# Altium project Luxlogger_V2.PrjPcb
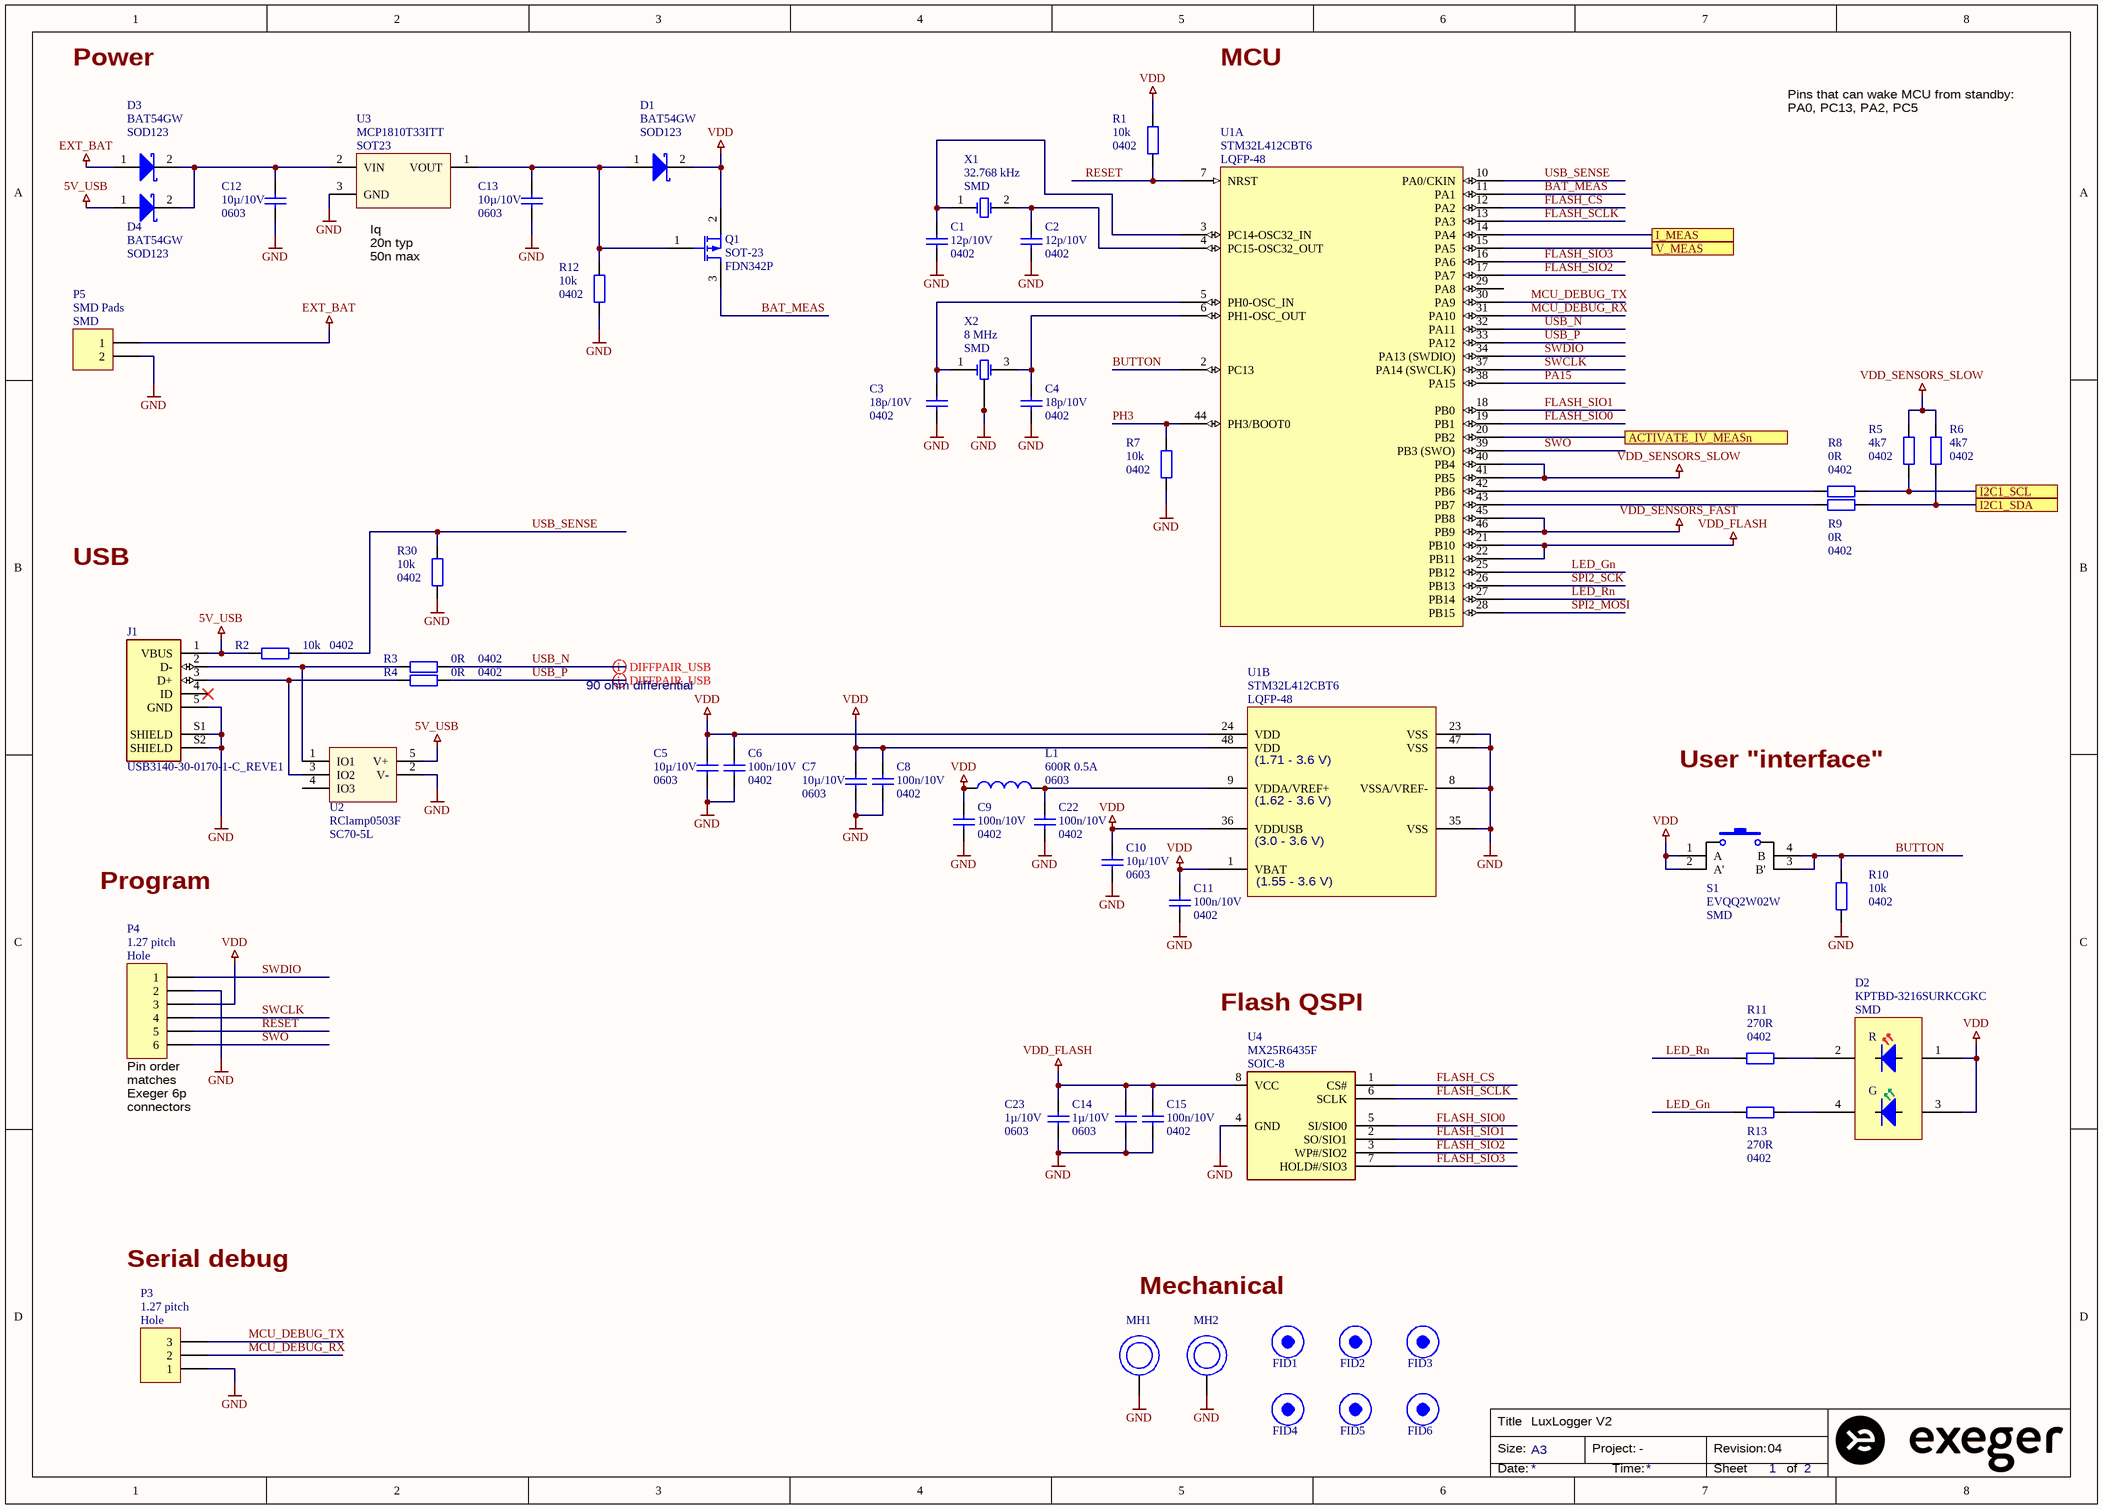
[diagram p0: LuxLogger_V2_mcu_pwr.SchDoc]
CompanyName: Exeger Operations AB; PROJ_Project: -; PROJ_Revision: 04; PROJ_Title: LuxLogger V2; Title: LuxLogger V2
3 sheets, 85 parts. Net scope: flat (ports and power ports of the same name join across sheets).
Board file: LuxLogger_V2_pcb.PcbDoc
Sheets:
  LuxLogger_V2_mcu_pwr.SchDoc
  LuxLogger_V2_sensors.SchDoc
  Sunboost.SchDoc

## Sheet LuxLogger_V2_mcu_pwr.SchDoc: LuxLogger V2
size A3; Engineer: ChEn; SheetNumber: 1; SheetTotal: 2

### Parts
(Parts that share a designator on the sheet are numbered #1, #2 ... from top to bottom, then left to right.)
C1  Specification: 12p/10V  Package: 0402  [CAP0402]
C2  Specification: 12p/10V  Package: 0402  [CAP0402]
C3  Specification: 18p/10V  Package: 0402  [CAP0402]
C4  Specification: 18p/10V  Package: 0402  [CAP0402]
C5  Specification: 10µ/10V  Package: 0603  [CAP0603]
C6  Specification: 100n/10V  Package: 0402  [CAP0402]
C7  Specification: 10µ/10V  Package: 0603  [CAP0603]
C8  Specification: 100n/10V  Package: 0402  [CAP0402]
C9  Specification: 100n/10V  Package: 0402  [CAP0402]
C10  Specification: 10µ/10V  Package: 0603  [CAP0603]
C11  Specification: 100n/10V  Package: 0402  [CAP0402]
C12  Specification: 10µ/10V  Package: 0603  [CAP0603]
C13  Specification: 10µ/10V  Package: 0603  [CAP0603]
C14  Specification: 1µ/10V  Package: 0603  [CAP0603]
C15  Specification: 100n/10V  Package: 0402  [CAP0402]
C22  Specification: 100n/10V  Package: 0402  [CAP0402]
C23  Specification: 1µ/10V  Package: 0603  [CAP0603]
D1  Package: SOD123  Specification: BAT54GW  [SOD123 SODFL360X130-2N]  (hidden comment: Alternative ON BAT54T1GOSCT-ND)
D2  Package: SMD  [KPTBD-3216SURKCGKC]
D3  Package: SOD123  Specification: BAT54GW  [SOD123 SODFL360X130-2N]  (hidden comment: Alternative ON BAT54T1GOSCT-ND)
D4  Package: SOD123  Specification: BAT54GW  [SOD123 SODFL360X130-2N]  (hidden comment: Alternative ON BAT54T1GOSCT-ND)
FID1  Fiducial  [FIDUCIAL_02_small]  (value not drawn)  (no BOM)
FID2  Fiducial  [FIDUCIAL_02_small]  (value not drawn)  (no BOM)
FID3  Fiducial  [FIDUCIAL_02_small]  (value not drawn)  (no BOM)
FID4  Fiducial  [FIDUCIAL_02_small]  (value not drawn)  (no BOM)
FID5  Fiducial  [FIDUCIAL_02_small]  (value not drawn)  (no BOM)
FID6  Fiducial  [FIDUCIAL_02_small]  (value not drawn)  (no BOM)
J1  USB3140-30-0170-1-C_REVE1  [GCT_USB3140-30-0170-1-C_REVE1]
L1  Specification: 600R 0.5A  Package: 0603  [CAP0603]
MH1  Mounting hole  [HOLE_PLATED_2300um]  (value not drawn)  (no BOM)
MH2  Mounting hole  [HOLE_PLATED_2300um]  (value not drawn)  (no BOM)
P3#1  Package: Hole  Specification: 1.27 pitch  [Header 1x3 1.27]  (no BOM)
P4  Package: Hole  Specification: 1.27 pitch  [Header 1x6 1.27]  (no BOM)
P5  Package: SMD  Specification: SMD Pads  [2x1 blank pads_2]  (no BOM)
Q1  Package: SOT-23  Specification: FDN342P  [SOT23-3]
R1  Package: 0402  Specification: 10k  [RES0402]
R2  Package: 0402  Specification: 10k  [RES0402]
R3  Package: 0402  Specification: 0R  [RES0402]
R4  Package: 0402  Specification: 0R  [RES0402]
R5  Package: 0402  Specification: 4k7  [RES0402]
R6  Package: 0402  Specification: 4k7  [RES0402]
R7  Package: 0402  Specification: 10k  [RES0402]
R8  Package: 0402  Specification: 0R  [RES0402]
R9  Package: 0402  Specification: 0R  [RES0402]
R10  Package: 0402  Specification: 10k  [RES0402]
R11  Package: 0402  Specification: 270R  [RES0402]
R12  Package: 0402  Specification: 10k  [RES0402]
R13  Package: 0402  Specification: 270R  [RES0402]
R30  Package: 0402  Specification: 10k  [RES0402]
S1  Package: SMD  [EVQQ2W02W]
U1  Specification: STM32L412CBT6  Package: LQFP-48  [TSQFP50P900X900X160-48N]  (parts A,B of 2)
U2  Package: SC70-5L  [SC-70 5L]
U3  Specification: MCP1810T33ITT  Package: SOT23  [SOT23-3]
U4  Package: SOIC-8  Specification: MX25R6435F  [SO_8_W]
X1  Package: SMD  Specification: 32.768 kHz  [FC-135]
X2  Specification: 8 MHz  Package: SMD  [ABM3B]

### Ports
ACTIVATE_IV_MEASn, I2C1_SCL, I2C1_SDA, I_MEAS, V_MEAS

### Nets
5V_USB: D4.1(A) J1.1(VBUS) R2.2 U2.5(V+)
EXT_BAT: D3.1(A) P5.1
GND: C1.1 C2.1 C3.1 C4.1 C5.1 C6.1 C7.1 C8.1 C9.1 C10.1 C11.1 C12.1 C13.1 C14.1 C15.1 C22.1 C23.1 J1.5(GND) J1.S1(SHIELD) J1.S2(SHIELD) MH1.1 MH2.1 P3#1.1 P4.2 P5.2 R7.1 R10.1 R12.1 R30.1 U1.8(VSSA/VREF-) U1.23(VSS) U1.35(VSS) U1.47(VSS) U2.2(V-) U3.3(GND) U4.4(GND) X2.2(GND) X2.4(GND)
VDD: C5.2 C6.2 C7.2 C8.2 C9.2 C10.2 C11.2 D1.2(K) D2.1(R_A) D2.3(G_A) L1.1 P4.3 Q1.2(S) R1.2 S1.1(A) S1.2(A') U1.1(VBAT) U1.24(VDD) U1.36(VDDUSB) U1.48(VDD)
VDD_FLASH: C14.2 C15.2 C23.2 U1.21(PB10) U1.22(PB11) U4.8(VCC)
VDD_SENSORS_FAST: U1.45(PB8) U1.46(PB9)
VDD_SENSORS_SLOW: R5.2 R6.2 U1.40(PB4) U1.41(PB5)
ACTIVATE_IV_MEASn: U1.20(PB2) ; port ACTIVATE_IV_MEASn
BAT_MEAS: Q1.3(D) U1.11(PA1)
BUTTON: R10.2 S1.3(B') S1.4(B) U1.2(PC13)
FLASH_CS: U1.12(PA2) U4.1(CS#)
FLASH_SCLK: U1.13(PA3) U4.6(SCLK)
FLASH_SIO0: U1.19(PB1) U4.5(SI/SIO0)
FLASH_SIO1: U1.18(PB0) U4.2(SO/SIO1)
FLASH_SIO2: U1.17(PA7) U4.3(WP#/SIO2)
FLASH_SIO3: U1.16(PA6) U4.7(HOLD#/SIO3)
I2C1_SCL: R5.1 R8.1 ; port I2C1_SCL
I2C1_SDA: R6.1 R9.1 ; port I2C1_SDA
I_MEAS: U1.14(PA4) ; port I_MEAS
LED_Gn: R13.2 U1.25(PB12)
LED_Rn: R11.2 U1.27(PB14)
MCU_DEBUG_RX: P3#1.2 U1.31(PA10)
MCU_DEBUG_TX: P3#1.3 U1.30(PA9)
PA15: U1.38(PA15)
PH3: R7.2 U1.44(PH3/BOOT0)
RESET: P4.5 R1.1 U1.7(NRST)
SPI2_MOSI: U1.28(PB15)
SPI2_SCK: U1.26(PB13)
SWCLK: P4.4 U1.37(PA14_(SWCLK))
SWDIO: P4.1 U1.34(PA13_(SWDIO))
SWO: P4.6 U1.39(PB3_(SWO))
USB_N: R3.1 U1.32(PA11)
USB_P: R4.1 U1.33(PA12)
USB_SENSE: R2.1 R30.2 U1.10(PA0/CKIN)
V_MEAS: U1.15(PA5) ; port V_MEAS
NetC1_2: C1.2 U1.3(PC14-OSC32_IN) X1.1(OSC1)
NetC2_2: C2.2 U1.4(PC15-OSC32_OUT) X1.2(OSC2)
NetC3_2: C3.2 U1.5(PH0-OSC_IN) X2.1(OSC1)
NetC4_2: C4.2 U1.6(PH1-OSC_OUT) X2.3(OSC2)
NetC12_2: C12.2 D3.2(K) D4.2(K) U3.2(VIN)
NetC13_2: C13.2 D1.1(A) Q1.1(G) R12.2 U3.1(VOUT)
NetC22_2: C22.2 L1.2 U1.9(VDDA/VREF+)
NetD2_2: D2.2(R_K) R11.1
NetD2_4: D2.4(G_K) R13.1
NetJ1_2: J1.2(D-) R3.2 U2.1(IO1)
NetJ1_3: J1.3(D+) R4.2 U2.3(IO2)
NetR8_2: R8.2 U1.42(PB6)
NetR9_2: R9.2 U1.43(PB7)

Not connected (* = marked no-connect by the designer): J1 4(ID)*; U1 29(PA8); U2 4(IO3)

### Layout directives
differential pair: USB_N, USB_P

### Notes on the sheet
- Power
- MCU
- Pins that can wake MCU from standby:
  PA0, PC13, PA2, PC5
- (near U3) Iq
  20n typ
  50n max
- USB
- 90 ohm differential
- User "interface"
- Program
- Flash QSPI
- (near P4) Pin order matches Exeger 6p connectors
- Serial debug
- Mechanical

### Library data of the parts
C1-C15 C22 C23 = Cap: Capacitor
D1 D3 D4 = D Schottky: Schottky Diode; Manufacturer: NEXPERIA
D2 = LED_RG: Red/green LED; Manufacturer: KINGBRIGHT
J1 = USB3140-30-0170-1-C_REVE1: USB - micro B USB 2.0 Receptacle Connector 5 Position Surface Mount, Through Hole; MF: Global Connector Technology
L1 = Inductor: Manufacturer PN: BLM18AG601SN1D; Manufacturer: MURATA
P3#1 = Header 3: Header, 3-Pin
P4 = Header 6: Header, 6-Pin
P5 = Header 2: Header, 2-Pin
Q1 = MOSFET-P: P-Channel MOSFET; Manufacturer: ON
R1-R13 R30 = Res2: Resistor
S1 = SW_EVQQ2: Switch; Manufacturer: PANASONIC
U1 = STM32L412CB_2: MCU; Manufacturer: ST
U2 = RClamp0503F: TVS array USB; Manufacturer: SEMTECH; Manufacturer PN: RClamp0503F.TCT
U3 = MCP1810TxxxTT: 3V3 LDO low iq; Manufacturer: MICROCHIP
U4 = MX25R6435F_SO8: ULTRA LOW POWER, 64M-BIT FLASH MEMORY; Manufacturer: Macronix; Manufacturer PN: MX25R6435FM2IL0
X1 = XTAL 2pin: 32.768 kHz Crystal; Manufacturer: EPSON; Manufacturer PN: FC-135 32.7680KA-A5
X2 = XTAL 4pin: Crystal; Manufacturer: ABRACON; Manufacturer PN: ABM3B-8.000MHZ-B2-T

## Sheet LuxLogger_V2_sensors.SchDoc: LuxLogger V2
size A3; Engineer: ChEn; SheetNumber: 2; SheetTotal: 2
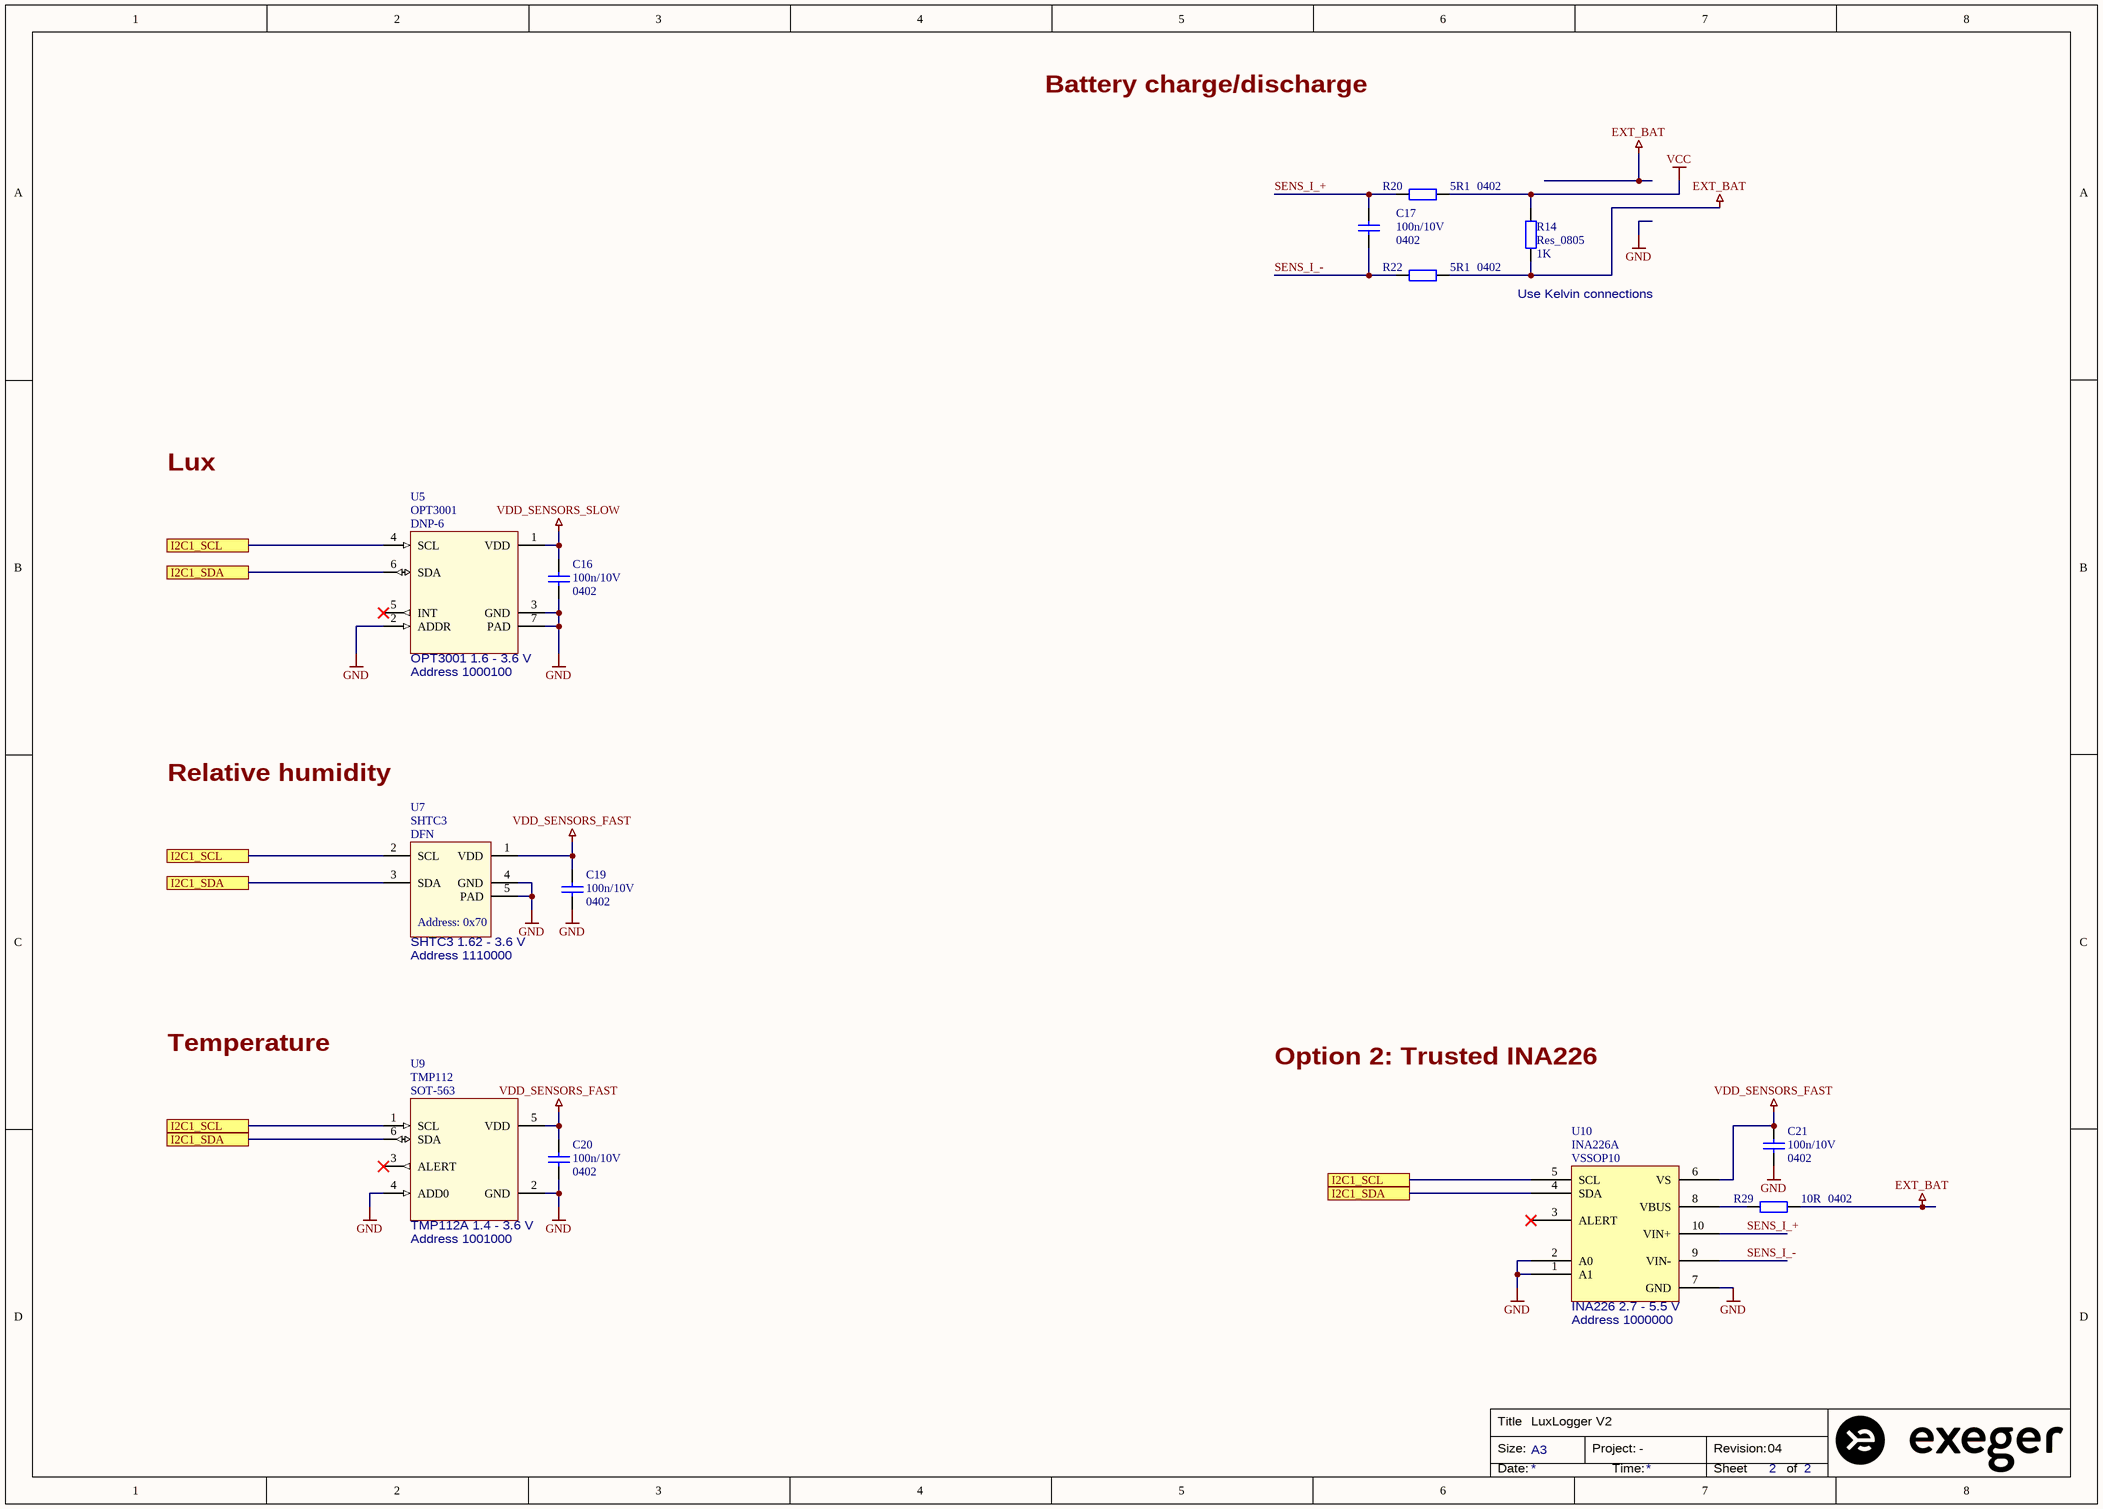
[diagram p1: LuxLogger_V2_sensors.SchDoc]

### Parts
C16  Specification: 100n/10V  Package: 0402  [CAP0402]
C17  Specification: 100n/10V  Package: 0402  [CAP0402]
C19  Specification: 100n/10V  Package: 0402  [CAP0402]
C20  Specification: 100n/10V  Package: 0402  [CAP0402]
C21  Specification: 100n/10V  Package: 0402  [CAP0402]
R14  Res_0805  value 1K  [0805]
R20  Package: 0402  Specification: 5R1  [RES0402]
R22  Package: 0402  Specification: 5R1  [RES0402]
R29  Package: 0402  Specification: 10R  [RES0402]
U5  Package: DNP-6  [OPT3001]
U7  Package: DFN  [SHTC3]
U9  Package: SOT-563  Specification: TMP112  [SOTFL50P160X60-6N]
U10  Package: VSSOP10  Specification: INA226A  [VSSOP-10]

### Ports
I2C1_SCL, I2C1_SDA

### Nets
EXT_BAT: R14.1 R22.1 R29.1
GND: C16.1 C19.1 C20.1 C21.1 U5.2(ADDR) U5.3(GND) U5.7(PAD) U7.4(GND) U7.5(PAD) U9.2(GND) U9.4(ADD0) U10.1(A1) U10.2(A0) U10.7(GND)
VCC: R14.2 R20.1
VDD_SENSORS_FAST: C19.2 C20.2 C21.2 U7.1(VDD) U9.5(VDD) U10.6(VS)
VDD_SENSORS_SLOW: C16.2 U5.1(VDD)
I2C1_SCL: U5.4(SCL) U7.2(SCL) U9.1(SCL) U10.5(SCL) ; port I2C1_SCL
I2C1_SDA: U5.6(SDA) U7.3(SDA) U9.6(SDA) U10.4(SDA) ; port I2C1_SDA
SENS_I_+: C17.2 R20.2 U10.10(VIN+)
SENS_I_-: C17.1 R22.2 U10.9(VIN-)
NetR29_2: R29.2 U10.8(VBUS)

Not connected (* = marked no-connect by the designer): U5 5(INT)*; U9 3(ALERT)*; U10 3(ALERT)*

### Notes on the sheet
- Battery charge/discharge
- (near R14) Use Kelvin connections
- Lux
- (near U5) Address 1000100
- (near U5) OPT3001 1.6 - 3.6 V
- Relative humidity
- (near U7) SHTC3 1.62 - 3.6 V
- Address 1110000
- Temperature
- Option 2: Trusted INA226
- (near U9) TMP112A 1.4 - 3.6 V
- (near U9) Address 1001000
- (near U10) Address 1000000
- (near U10) INA226 2.7 - 5.5 V

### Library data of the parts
C16 C17 C19-C21 = Cap: Capacitor
R14 = Res_0805: Resistor
R20 R22 R29 = Res2: Resistor
U5 = OPT3001: Lux sensor; Manufacturer: TI; Manufacturer PN: OPT3001DNP
U7 = SHTC3: SHTC3 RH sensor; Manufacturer: SENSIRION
U9 = TMP112A: Temp_Sensor; Manufacturer: TI; Manufacturer PN: TMP112AIDR
U10 = INA226: Current and power monitor; Manufacturer PN: INA226AIDGS; Manufacturer: TI

## Sheet Sunboost.SchDoc: LuxLogger V2
size A3; Organization: Altium Limited; Address1: L3, 12a Rodborough Rd; Address2: Frenchs Forest; Address3: NSW; Address4: Australia 2086
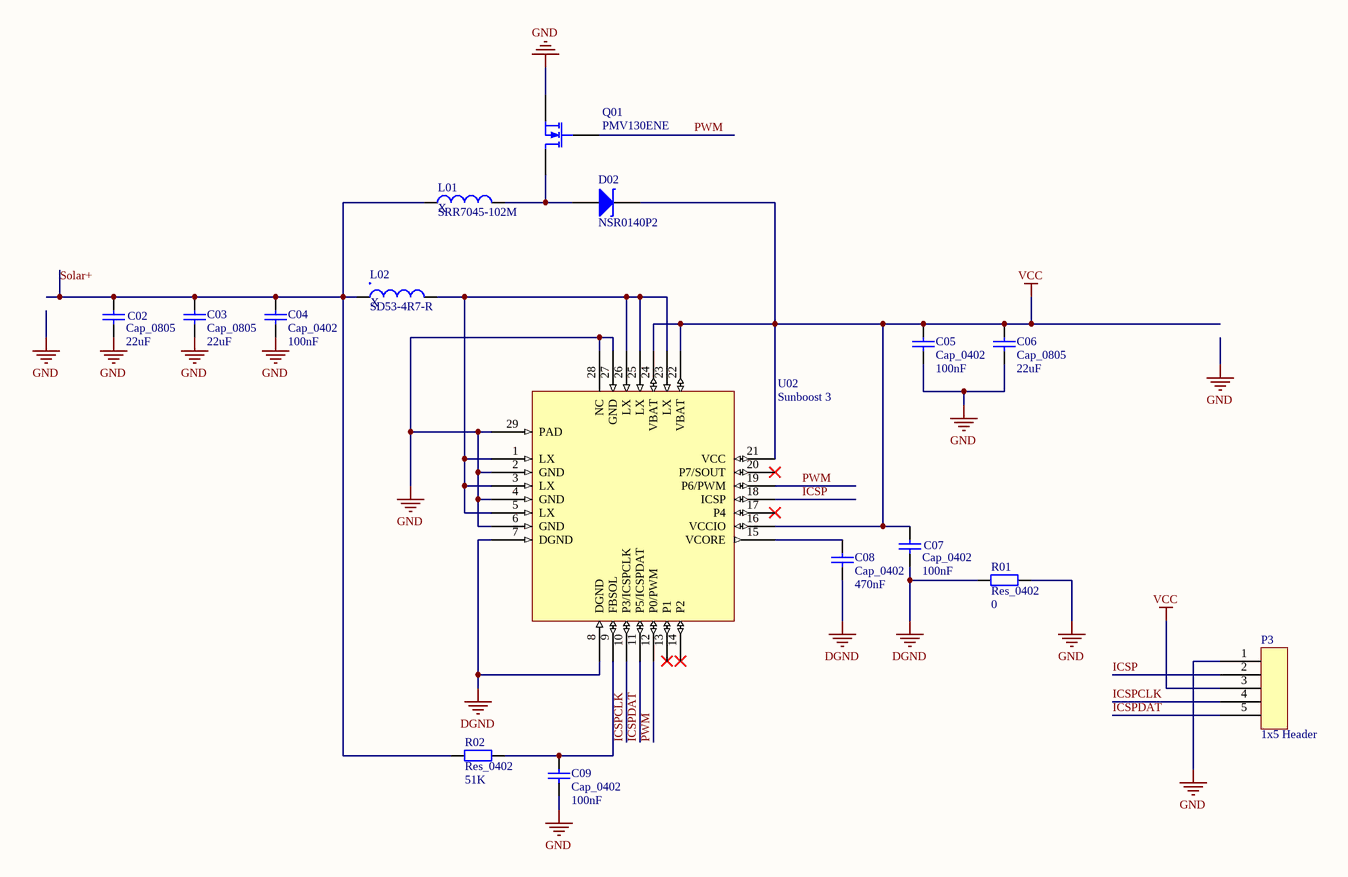
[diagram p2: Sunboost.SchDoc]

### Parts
(Parts that share a designator on the sheet are numbered #1, #2 ... from top to bottom, then left to right.)
C02  Cap_0805  value 22uF  [0805]
C03  Cap_0805  value 22uF  [0805]
C04  Cap_0402  value 100nF  [0402]
C05  Cap_0402  value 100nF  [0402]
C06  Cap_0805  value 22uF  [0805]
C07  Cap_0402  value 100nF  [0402]
C08  Cap_0402  value 470nF  [0402]
C09  Cap_0402  value 100nF  [0402]
D02  NSR0140P2  [SOD-923]
L01  SRR7045-102M  value X  [SRR7045-102M]
L02  SD53-4R7-R  value X  [SD53-4R7-R]
P3#2  1x5 Header  [1x5 Header 1.27]
Q01  PMV130ENE  [SOT-23]
R01  Res_0402  value 0  [0402]
R02  Res_0402  value 51K  [0402]
U02  Sunboost 3  [28-QFN_0.4mm]

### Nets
DGND: C07.1 C08.1 R01.1 U02.7(DGND) U02.8(DGND)
GND: C02.1 C03.1 C04.1 C05.1 C06.1 C09.1 P3#2.1 Q01.2(S) R01.2 U02.2(GND) U02.4(GND) U02.6(GND) U02.27(GND) U02.28(NC) U02.29(PAD)
VCC: C05.2 C06.2 C07.2 D02.1(K) P3#2.3 U02.16(VCCIO) U02.21(VCC) U02.22(VBAT) U02.24(VBAT)
ICSP: P3#2.2 U02.18(ICSP)
ICSPCLK: P3#2.4 U02.10(P3/ICSPCLK)
ICSPDAT: P3#2.5 U02.11(P5/ICSPDAT)
PWM: Q01.1(G) U02.12(P0/PWM) U02.19(P6/PWM)
Solar+: C02.2 C03.2 C04.2 L01.1 L02.1 R02.1
NetC08_2: C08.2 U02.15(VCORE)
NetC09_2: C09.2 R02.2 U02.9(FBSOL)
NetD02_2: D02.2(A) L01.2 Q01.3(D)
NetL02_2: L02.2 U02.1(LX) U02.3(LX) U02.5(LX) U02.23(LX) U02.25(LX) U02.26(LX)

Not connected (* = marked no-connect by the designer): U02 13(P1)* 14(P2)* 17(P4)* 20(P7/SOUT)*

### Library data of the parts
C02 C03 C06 = Cap_0805: Capacitor
C04 C05 C07 C08 C09 = Cap_0402: Capacitor
D02 = NSR0140P2: Typical INFRARED GaAs LED
L01 = SRR7045-102M: Inductor
L02 = SD53-4R7-R: Inductor
Q01 = PMV130ENE: N-Channel MOSFET
R01 R02 = Res_0402: Resistor
U02 = Sunboost 3: Initvation Sunboost 3

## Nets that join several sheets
EXT_BAT: LuxLogger_V2_mcu_pwr (D3.1 P5.1), LuxLogger_V2_sensors (R14.1 R22.1 R29.1)
GND: LuxLogger_V2_mcu_pwr (38 pins), LuxLogger_V2_sensors (14 pins), Sunboost (15 pins)
VCC: LuxLogger_V2_sensors (R14.2 R20.1), Sunboost (9 pins)
VDD_SENSORS_FAST: LuxLogger_V2_mcu_pwr (U1.45 U1.46), LuxLogger_V2_sensors (6 pins)
VDD_SENSORS_SLOW: LuxLogger_V2_mcu_pwr (R5.2 R6.2 U1.40 U1.41), LuxLogger_V2_sensors (C16.2 U5.1)
I2C1_SCL: LuxLogger_V2_mcu_pwr (R5.1 R8.1), LuxLogger_V2_sensors (U5.4 U7.2 U9.1 U10.5)
I2C1_SDA: LuxLogger_V2_mcu_pwr (R6.1 R9.1), LuxLogger_V2_sensors (U5.6 U7.3 U9.6 U10.4)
